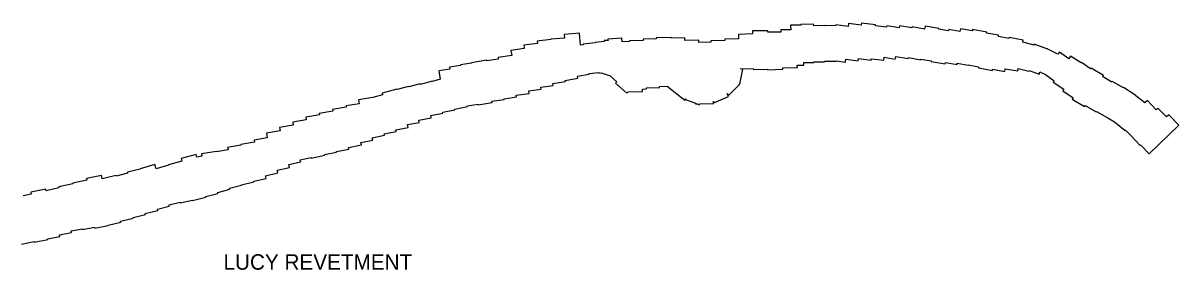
# Model space of a CAD drawing. Extents: x 2650582 to 3923188, y 277893 to 989177.
# Drawn here: x 3536865 to 3548804, y 562181 to 564731 of the extents above; entities that cross this region are included whole.
import ezdxf

# ---------------------------------------------------------------- set-up
doc = ezdxf.new("R2010")
doc.units = 0
doc.layers.add('Level 3', color=7, linetype='Continuous')

msp = doc.modelspace()

# ---------------------------------------------------------------- linework, layer by layer
at = {"layer": 'Level 3'}
for points in [[(3542622, 564503), (3542611, 564626), (3542453, 564612), (3542456, 564577), (3542315, 564564), (3542315, 564562), (3542174, 564545), (3542177, 564521), (3542037, 564502), (3542041, 564468), (3541904, 564449), (3541912, 564397), (3541771, 564376), (3541773, 564360), (3541656, 564342), (3541655, 564349), (3541497, 564321), (3541498, 564316), (3541382, 564299), (3541383, 564293), (3541270, 564277), (3541274, 564254), (3541161, 564237)], [(3544794, 564709), (3544795, 564663), (3544694, 564661), (3544694, 564639), (3544558, 564636), (3544557, 564653), (3544399, 564650), (3544400, 564619), (3544255, 564615), (3544256, 564570), (3544114, 564566), (3544115, 564550), (3543969, 564547), (3543969, 564533), (3543847, 564531), (3543847, 564554), (3543701, 564550), (3543701, 564579), (3543563, 564575), (3543563, 564583), (3543406, 564579), (3543406, 564567), (3543270, 564564), (3543271, 564553), (3543130, 564547), (3543130, 564541), (3543054, 564538)], [(3548496, 563381), (3548804, 563675), (3548699, 563785), (3548675, 563763), (3548588, 563853), (3548570, 563836), (3548480, 563930), (3548454, 563906), (3548359, 563981), (3548360, 563982), (3548234, 564065), (3548232, 564061), (3548116, 564128), (3548113, 564122), (3548017, 564178), (3548024, 564189), (3547897, 564266), (3547893, 564260), (3547797, 564323), (3547794, 564319), (3547685, 564391), (3547667, 564363), (3547570, 564431), (3547554, 564409), (3547450, 564462), (3547450, 564463), (3547447, 564464), (3547440, 564467), (3547440, 564466), (3547311, 564512), (3547309, 564504), (3547191, 564533), (3547195, 564555), (3547050, 564581), (3547049, 564573), (3546940, 564592), (3546942, 564605), (3546816, 564627), (3546819, 564639), (3546674, 564664), (3546671, 564651), (3546547, 564673), (3546542, 564646), (3546428, 564666), (3546426, 564651), (3546325, 564668), (3546326, 564674), (3546183, 564699), (3546178, 564670), (3546049, 564693), (3546047, 564681), (3545919, 564704), (3545915, 564681), (3545786, 564704), (3545783, 564689), (3545669, 564703), (3545670, 564713), (3545525, 564731), (3545522, 564710), (3545391, 564727), (3545388, 564697), (3545260, 564713), (3545259, 564705), (3545141, 564704), (3545141, 564706), (3545032, 564704), (3545031, 564720), (3544898, 564718), (3544898, 564710), (3544794, 564709)], [(3543054, 564538), (3543050, 564577), (3542906, 564564), (3542907, 564552), (3542866, 564551), (3542866, 564542), (3542775, 564531), (3542775, 564529), (3542650, 564514), (3542651, 564508), (3542622, 564503)], [(3544862, 564297), (3544931, 564298), (3544931, 564323), (3545035, 564324), (3545035, 564330), (3545145, 564331), (3545145, 564338), (3545269, 564339), (3545269, 564341), (3545360, 564329), (3545364, 564359), (3545491, 564343), (3545494, 564364), (3545625, 564348), (3545627, 564363), (3545756, 564347), (3545760, 564380), (3545874, 564360), (3545879, 564386), (3546007, 564364), (3546010, 564375), (3546138, 564353), (3546139, 564359), (3546247, 564340), (3546246, 564334), (3546390, 564309), (3546392, 564324), (3546513, 564303), (3546515, 564317), (3546629, 564297), (3546629, 564299), (3546735, 564281), (3546733, 564268), (3546878, 564243), (3546880, 564254), (3547007, 564232), (3547011, 564259), (3547139, 564237), (3547143, 564263), (3547256, 564236), (3547257, 564241), (3547360, 564205), (3547368, 564229), (3547425, 564199), (3547517, 564135), (3547507, 564120), (3547616, 564048), (3547605, 564030), (3547711, 563960), (3547702, 563945), (3547829, 563868), (3547836, 563880), (3547951, 563813), (3547954, 563819), (3548070, 563751), (3548072, 563754), (3548138, 563711), (3548249, 563623), (3548252, 563626), (3548314, 563562), (3548315, 563563), (3548405, 563468), (3548409, 563472), (3548496, 563381)], [(3542931, 564185), (3542999, 564126), (3542984, 564109), (3543101, 564007), (3543115, 564022), (3543262, 564025), (3543262, 564050), (3543306, 564052), (3543306, 564061), (3543440, 564065), (3543439, 564076), (3543517, 564078), (3543517, 564078), (3543701, 563935), (3543710, 563947), (3543709, 563943), (3543811, 563903), (3543811, 563897), (3543827, 563897), (3543849, 563888), (3543852, 563897), (3543996, 563900), (3543996, 563923), (3544002, 563909), (3544151, 563973), (3544138, 564004), (3544155, 563987), (3544266, 564096), (3544259, 564103), (3544270, 564101), (3544301, 564254), (3544274, 564260), (3544408, 564263), (3544409, 564252), (3544556, 564255), (3544556, 564250), (3544713, 564254), (3544713, 564270), (3544863, 564274), (3544862, 564297)], [(3540355, 563497), (3540476, 563523), (3540471, 563545), (3540599, 563572), (3540596, 563586), (3540718, 563612), (3540715, 563627), (3540844, 563654), (3540837, 563683), (3540957, 563705), (3540953, 563728), (3541081, 563752), (3541076, 563777), (3541202, 563800), (3541200, 563811), (3541325, 563834), (3541324, 563843), (3541457, 563868), (3541456, 563876), (3541566, 563893), (3541567, 563888), (3541710, 563910), (3541708, 563923), (3541835, 563942), (3541834, 563950), (3541962, 563969), (3541960, 563985), (3542092, 564005), (3542089, 564030), (3542216, 564049), (3542213, 564068), (3542340, 564087), (3542337, 564107), (3542468, 564127), (3542466, 564139), (3542597, 564162), (3542593, 564184), (3542712, 564205), (3542711, 564210), (3542811, 564222), (3542812, 564214), (3542836, 564217), (3542931, 564185)], [(3541161, 564237), (3541174, 564151), (3541095, 564129), (3541094, 564132), (3540968, 564096), (3540966, 564104), (3540848, 564071), (3540846, 564077), (3540728, 564045), (3540727, 564049), (3540574, 564006), (3540579, 563990), (3540478, 563962)], [(3540478, 563962), (3540330, 563937), (3540336, 563898), (3540201, 563875), (3540203, 563864), (3540061, 563840), (3540064, 563820), (3539923, 563796), (3539926, 563784), (3539785, 563760), (3539790, 563731), (3539651, 563707), (3539656, 563678), (3539514, 563653), (3539520, 563619), (3539378, 563595), (3539387, 563546), (3539251, 563523), (3539255, 563500), (3539114, 563476), (3539115, 563470), (3538978, 563447), (3538983, 563420), (3538864, 563400), (3538863, 563406), (3538709, 563379), (3538712, 563356), (3538659, 563347)], [(3536848, 562448), (3536978, 562473), (3536979, 562468), (3537120, 562496), (3537119, 562503), (3537243, 562527), (3537240, 562542), (3537366, 562567), (3537363, 562584), (3537477, 562606), (3537479, 562597), (3537603, 562621), (3537605, 562612), (3537745, 562639), (3537744, 562644), (3537875, 562675), (3537872, 562685), (3538003, 562716), (3538001, 562723), (3538128, 562754), (3538126, 562763), (3538255, 562794), (3538252, 562809), (3538375, 562838), (3538372, 562853), (3538487, 562880), (3538489, 562873), (3538614, 562903), (3538616, 562897), (3538754, 562933), (3538752, 562939), (3538877, 562972), (3538875, 562980), (3539001, 563014), (3538998, 563026), (3539122, 563057), (3539121, 563061), (3539249, 563091), (3539248, 563097), (3539376, 563127), (3539370, 563154), (3539495, 563183), (3539489, 563210), (3539617, 563239), (3539610, 563269), (3539732, 563298), (3539728, 563318), (3539839, 563341), (3539840, 563336), (3539981, 563365), (3539979, 563372), (3540104, 563398), (3540103, 563403), (3540230, 563430), (3540227, 563445), (3540360, 563474), (3540355, 563497)], [(3538659, 563347), (3538652, 563375), (3538498, 563333), (3538506, 563306), (3538368, 563267), (3538368, 563264), (3538238, 563227), (3538226, 563270), (3538073, 563227), (3538074, 563223), (3537942, 563190), (3537944, 563180), (3537825, 563151), (3537824, 563155), (3537681, 563123), (3537673, 563157), (3537520, 563124), (3537523, 563109), (3537377, 563078), (3537379, 563071), (3537233, 563038), (3537235, 563029), (3537102, 562999), (3537098, 563017), (3536944, 562983), (3536948, 562965), (3536865, 562947)]]:
    msp.add_lwpolyline(points, dxfattribs=at)

# ---------------------------------------------------------------- texts
msp.add_text('LUCY REVETMENT', height=160, dxfattribs=at).set_placement((3538935, 562183))

doc.saveas('drawing.dxf')
